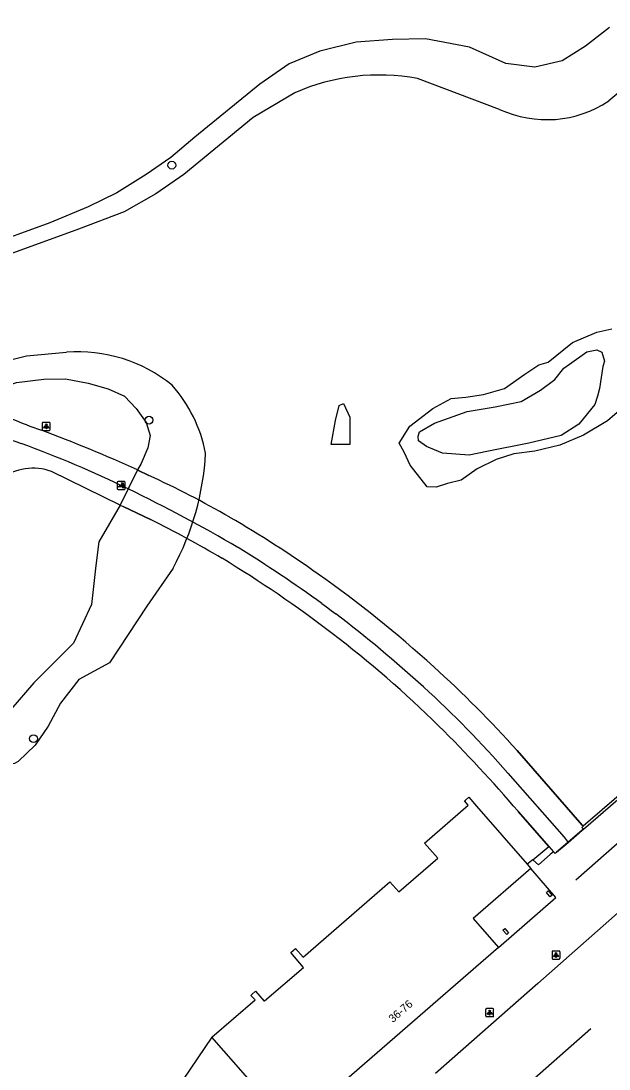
# Model space of a CAD drawing. Extents: x 155640 to 156810, y 382822 to 384046.
# Drawn here: x 156439.7 to 156513.2, y 383789.4 to 383920.4 of the extents above; entities that cross this region are included whole.
import ezdxf

# ---------------------------------------------------------------- set-up
doc = ezdxf.new("R2010")
doc.units = 0
for name, color, linetype in [('IMGEO_Boom', 7, 'Continuous'), ('IMGEO_Dek', 7, 'Continuous'), ('IMGEO_Fietspad_gesloten', 7, 'Continuous'), ('IMGEO_Grasland_overig', 7, 'Continuous'), ('IMGEO_Groenvoorziening', 7, 'Continuous'), ('IMGEO_Hek', 7, 'Continuous'), ('IMGEO_Lichtpunt', 7, 'Continuous'), ('IMGEO_Lijnafwatering', 7, 'Continuous'), ('IMGEO_Meer_plas_ven_vijver', 7, 'Continuous'), ('IMGEO_Muur', 7, 'Continuous'), ('IMGEO_Pand', 7, 'Continuous'), ('IMGEO_Pand_nummerreeks', 7, 'Continuous'), ('IMGEO_Pand_overbouw', 7, 'Continuous'), ('IMGEO_Poller', 7, 'Continuous'), ('IMGEO_Voetgangersgebied_open', 7, 'Continuous'), ('IMGEO_Voetpad_gesloten', 7, 'Continuous')]:
    doc.layers.add(name, color=color, linetype=linetype)

msp = doc.modelspace()

# ---------------------------------------------------------------- linework, layer by layer
at = {"layer": 'IMGEO_Boom'}
for centre in [(156458.58, 383902.33), (156455.73, 383870.47), (156441.3, 383830.68)]:
    msp.add_circle(centre, 0.489, dxfattribs=at)
at = {"layer": 'IMGEO_Dek'}
for points in [[(156455.71, 383863.56), (156454.33, 383864.24), (156454.27, 383864.27), (156452.13, 383859.87), (156452.48, 383859.7), (156455.93, 383858.04)], [(156501.83, 383821.59), (156505.68, 383817.2), (156506.27, 383816.55), (156506.48, 383816.34), (156506.64, 383816.48), (156508.08, 383817.72), (156509.85, 383819.25), (156510.01, 383819.38), (156509.8, 383819.59), (156509.97, 383819.73), (156509.84, 383819.88), (156501.72, 383829.19)]]:
    msp.add_lwpolyline(points, dxfattribs=at)
for centre, radius, start, end in [((156407.64, 383758.31), 115.71, 59.8229, 65.456), ((156388.52, 383723.16), 150.79, 59.5873, 63.4458), ((156397.92, 383740.52), 135.97, 54.5063, 60.0478), ((156387.28, 383724.79), 150.03, 52.507, 58.8657), ((156394.44, 383733.64), 143.59, 47.5855, 54.9701), ((156392.74, 383731.25), 141.57, 45.5357, 52.6667), ((156398.64, 383736.95), 138.32, 41.8243, 47.9452), ((156370.38, 383709.63), 172.67, 40.4232, 45.2677)]:
    msp.add_arc(centre, radius, start, end, dxfattribs=at)
at = {"layer": 'IMGEO_Fietspad_gesloten'}
for points in [[(156454.27, 383864.27), (156453.11, 383861.89)], [(156455.71, 383863.56), (156454.33, 383864.24), (156454.27, 383864.27), (156453.11, 383861.89)], [(156477.31, 383847.56), (156477.9, 383847.13), (156478.49, 383846.7), (156479.08, 383846.26)], [(156508.08, 383817.72), (156509.85, 383819.25), (156510.01, 383819.38), (156509.8, 383819.59), (156509.97, 383819.73), (156509.84, 383819.88), (156501.72, 383829.19)], [(156500.57, 383826.38), (156507.58, 383818.36), (156508.08, 383817.72)]]:
    msp.add_lwpolyline(points, dxfattribs=at)
for centre, radius, start, end in [((156459.34, 383918.52), 52.18, 241.9205, 250.9257), ((156449.16, 383897.12), 31.01, 236.13, 252.313), ((156376.78, 383693.33), 187.68, 65.6141, 69.5712), ((156391.29, 383734.93), 141.21, 64.034, 69.9343), ((156407.64, 383758.31), 115.71, 59.8229, 65.456), ((156374.93, 383698.79), 180.86, 59.4572, 64.3905), ((156397.92, 383740.52), 135.97, 54.5063, 60.0478), ((156382.67, 383717.37), 160.95, 53.9824, 58.4658), ((156394.44, 383733.64), 143.59, 47.5855, 54.9701), ((156371.97, 383706.5), 176.08, 47.895, 52.536), ((156398.64, 383736.95), 138.32, 41.8243, 47.9452), ((156396.79, 383735.25), 138.11, 41.2853, 47.5365)]:
    msp.add_arc(centre, radius, start, end, dxfattribs=at)
at = {"layer": 'IMGEO_Grasland_overig'}
msp.add_lwpolyline([(156512.42, 383877.17), (156512.02, 383874.44), (156511.75, 383873.47), (156511.42, 383872.41), (156509.4, 383869.98), (156507.21, 383868.56), (156503.16, 383867.58), (156497.93, 383866.55), (156495.73, 383866.11), (156492.38, 383866.36), (156490.38, 383867.17), (156489.39, 383867.89), (156489.37, 383868.49), (156489.52, 383869.02), (156491.38, 383870.11), (156495.49, 383871.54), (156498.98, 383872.15), (156502.2, 383872.79), (156504.62, 383874.2), (156506.42, 383875.56), (156507.56, 383876.98), (156508.24, 383877.46), (156510.42, 383879.01), (156511.66, 383879.24), (156512.3, 383878.96), (156512.62, 383877.83), (156512.42, 383877.17)], dxfattribs=at)
at = {"layer": 'IMGEO_Groenvoorziening'}
for points in [[(156513.23, 383919.55), (156510.25, 383917.22), (156507.34, 383915.39), (156503.94, 383914.57), (156500.29, 383915.04), (156495.77, 383917.07), (156490.27, 383918.13), (156486.14, 383918.02), (156481.59, 383917.7), (156477.06, 383916.59), (156473.23, 383914.99), (156469.59, 383912.45), (156461.46, 383905.85), (156458.47, 383903.31), (156455.37, 383901.16), (156451.69, 383898.86), (156448.12, 383897.12), (156443.34, 383895.14), (156434.84, 383892.06)], [(156434.78, 383872.48), (156436.85, 383874.43), (156439.16, 383875.17), (156442.59, 383875.59), (156445.3, 383875.64), (156448.14, 383875.08), (156450.64, 383874.39), (156452.65, 383873.49), (156454.13, 383871.92), (156455.37, 383870.16), (156455.88, 383868.55), (156455.6, 383867.01), (156454.74, 383865.07), (156454.27, 383864.27)], [(156452.13, 383859.87), (156449.48, 383855.27), (156449.08, 383852.3), (156448.55, 383847.43), (156446.31, 383842.6), (156441.33, 383837.65), (156438.48, 383834.31), (156437.94, 383832.12), (156437.62, 383830.06), (156437.35, 383827.77)]]:
    msp.add_lwpolyline(points, dxfattribs=at)
at = {"layer": 'IMGEO_Hek'}
for points in [[(156454.33, 383864.24), (156455.71, 383863.56)], [(156452.13, 383859.87), (156452.48, 383859.7)], [(156455.93, 383858.04), (156452.48, 383859.7)], [(156501.72, 383829.19), (156509.84, 383819.88)], [(156505.68, 383817.2), (156501.83, 383821.59)], [(156509.84, 383819.88), (156509.97, 383819.73)]]:
    msp.add_lwpolyline(points, dxfattribs=at)
for centre, radius, start, end in [((156407.64, 383758.31), 115.71, 59.8229, 65.456), ((156388.52, 383723.16), 150.79, 59.5873, 63.4458), ((156397.92, 383740.52), 135.97, 54.5063, 60.0478), ((156387.28, 383724.79), 150.03, 52.507, 58.8657), ((156394.44, 383733.64), 143.59, 47.5855, 54.9701), ((156392.74, 383731.25), 141.57, 45.5357, 52.6667), ((156398.64, 383736.95), 138.32, 41.8243, 47.9452), ((156370.38, 383709.63), 172.67, 40.4232, 45.2677)]:
    msp.add_arc(centre, radius, start, end, dxfattribs=at)
at = {"layer": 'IMGEO_Lichtpunt'}
for p, q in [((156442.39, 383870.11), (156442.39, 383869.3)), ((156442.39, 383870.11), (156442.39, 383869.3)), ((156443.29, 383870.2), (156442.48, 383870.2)), ((156443.29, 383870.2), (156442.48, 383870.2)), ((156442.48, 383869.2), (156443.29, 383869.2)), ((156442.48, 383869.2), (156443.29, 383869.2)), ((156443.38, 383869.3), (156443.38, 383870.11)), ((156443.38, 383869.3), (156443.38, 383870.11)), ((156506.07, 383804.04), (156506.07, 383803.23)), ((156506.07, 383804.04), (156506.07, 383803.23)), ((156506.97, 383804.13), (156506.17, 383804.13)), ((156506.97, 383804.13), (156506.17, 383804.13)), ((156507.07, 383803.23), (156507.07, 383804.04)), ((156507.07, 383803.23), (156507.07, 383804.04)), ((156506.17, 383803.14), (156506.97, 383803.14)), ((156506.17, 383803.14), (156506.97, 383803.14)), ((156497.78, 383796.85), (156497.78, 383796.04)), ((156497.78, 383796.85), (156497.78, 383796.04)), ((156498.69, 383796.95), (156497.88, 383796.95)), ((156498.69, 383796.95), (156497.88, 383796.95)), ((156497.88, 383795.95), (156498.69, 383795.95)), ((156497.88, 383795.95), (156498.69, 383795.95)), ((156498.78, 383796.04), (156498.78, 383796.85)), ((156498.78, 383796.04), (156498.78, 383796.85))]:
    msp.add_line(p, q, dxfattribs=at)
for points in [[(156442.76, 383869.77), (156442.8, 383869.74), (156442.61, 383869.48), (156442.57, 383869.51), (156442.76, 383869.77)], [(156442.86, 383869.72), (156442.91, 383869.72), (156442.91, 383869.4), (156442.86, 383869.4), (156442.86, 383869.72)], [(156442.97, 383869.74), (156443.01, 383869.77), (156443.2, 383869.51), (156443.16, 383869.48), (156442.97, 383869.74)], [(156506.45, 383803.7), (156506.49, 383803.67), (156506.3, 383803.41), (156506.26, 383803.44), (156506.45, 383803.7)], [(156506.55, 383803.65), (156506.6, 383803.65), (156506.6, 383803.33), (156506.55, 383803.33), (156506.55, 383803.65)], [(156506.66, 383803.67), (156506.7, 383803.7), (156506.88, 383803.44), (156506.85, 383803.41), (156506.66, 383803.67)], [(156498.16, 383796.51), (156498.2, 383796.49), (156498.01, 383796.22), (156497.97, 383796.25), (156498.16, 383796.51)], [(156498.26, 383796.47), (156498.31, 383796.47), (156498.31, 383796.14), (156498.26, 383796.14), (156498.26, 383796.47)], [(156498.37, 383796.49), (156498.41, 383796.51), (156498.6, 383796.25), (156498.56, 383796.22), (156498.37, 383796.49)]]:
    msp.add_lwpolyline(points, dxfattribs=at)
for centre in [(156442.89, 383869.9), (156506.57, 383803.84), (156498.28, 383796.65)]:
    msp.add_circle(centre, 0.0994, dxfattribs=at)
for centre, start, end in [((156442.48, 383870.11), 90, 180), ((156442.48, 383870.11), 90, 180), ((156442.48, 383869.3), 180, 270), ((156442.48, 383869.3), 180, 270), ((156443.29, 383870.11), 0, 90), ((156443.29, 383870.11), 0, 90), ((156443.29, 383869.3), 270, 0), ((156443.29, 383869.3), 270, 360), ((156506.17, 383804.04), 90, 180), ((156506.17, 383804.04), 90, 180), ((156506.97, 383804.04), 0, 90), ((156506.97, 383804.04), 0, 90), ((156506.17, 383803.23), 180, 270), ((156506.17, 383803.23), 180, 270), ((156506.97, 383803.23), 270, 0), ((156506.97, 383803.23), 270, 360), ((156497.88, 383796.85), 90, 180), ((156497.88, 383796.85), 90, 180), ((156497.88, 383796.04), 180, 270), ((156497.88, 383796.04), 180, 270), ((156498.69, 383796.85), 0, 90), ((156498.69, 383796.85), 0, 90), ((156498.69, 383796.04), 270, 0), ((156498.69, 383796.04), 270, 360)]:
    msp.add_arc(centre, 0.0946, start, end, dxfattribs=at)
at = {"layer": 'IMGEO_Lijnafwatering'}
for points in [[(156518.01, 383820.86), (156509.03, 383812.99)], [(156517.1, 383811.35), (156504.3, 383800.09)], [(156504.3, 383800.09), (156491.53, 383788.85)], [(156498.95, 383783.94), (156510.91, 383794.44)]]:
    msp.add_lwpolyline(points, dxfattribs=at)
at = {"layer": 'IMGEO_Meer_plas_ven_vijver'}
for points in [[(156525.12, 383920.35), (156513.17, 383910.36)], [(156499.53, 383909.31), (156489.26, 383913.17)], [(156473.95, 383911.38), (156468.73, 383908.3), (156460.07, 383901.16), (156456.57, 383898.77), (156452.63, 383896.51), (156446.94, 383894.32), (156435.55, 383890.23), (156429.43, 383888.05), (156419.86, 383885.57), (156417.85, 383884.58), (156412.79, 383883.05), (156406.5, 383879.69)], [(156499.08, 383865.54), (156496.7, 383864.39), (156494.74, 383862.97), (156493.03, 383862.54), (156491.61, 383862.11), (156490.46, 383862.13), (156488.33, 383864.83), (156487.61, 383866.48), (156486.97, 383867.61), (156488.32, 383869.73), (156491.19, 383871.95), (156493.49, 383873.18), (156495.3, 383873.34), (156497.52, 383873.67), (156500.15, 383874.41), (156502.69, 383876.22), (156504.42, 383877.37), (156505.57, 383877.7), (156508.61, 383880.16), (156511.65, 383881.47), (156513.54, 383881.88)], [(156422.64, 383871.06), (156424.67, 383872.17), (156429.66, 383875.18), (156435.26, 383877.22), (156440.44, 383878.51), (156445.43, 383878.97)], [(156479.04, 383870.43), (156479.49, 383872.31), (156480.03, 383872.56), (156480.83, 383870.83), (156480.83, 383867.42), (156478.47, 383867.42), (156479.04, 383870.43)], [(156515.1, 383872.19), (156513, 383870.37), (156510, 383868.58), (156507.05, 383867.35), (156503.93, 383866.61), (156501.3, 383866.28), (156499.08, 383865.54)], [(156458.74, 383851.99), (156455.47, 383847.25), (156450.79, 383840.16), (156446.97, 383838.07), (156444.69, 383835.11), (156443.15, 383832.25), (156441.52, 383829.86), (156439.38, 383827.8), (156438.92, 383827.57), (156438.51, 383827.51), (156437.96, 383827.59), (156437.35, 383827.77)]]:
    msp.add_lwpolyline(points, dxfattribs=at)
for centre, radius, start, end in [((156484.5, 383887.41), 26.19, 79.5305, 113.7702), ((156505.4, 383922.07), 14.05, 245.2987, 303.5585), ((156446.8, 383860.24), 18.78, 51.0389, 94.1926), ((156445.17, 383862.94), 17.95, 10.93, 41.535), ((156428.85, 383868.21), 34, 331.5161, 356.8601)]:
    msp.add_arc(centre, radius, start, end, dxfattribs=at)
at = {"layer": 'IMGEO_Muur'}
for points in [[(156520.99, 383827.32), (156518.61, 383827.19), (156512.33, 383821.77), (156509.97, 383819.73), (156509.8, 383819.59), (156510.01, 383819.38)], [(156510.01, 383819.38), (156518.56, 383826.76), (156518.72, 383826.9), (156521, 383827.02)], [(156503.68, 383815.54), (156505.68, 383817.2), (156506.27, 383816.55)], [(156506.27, 383816.55), (156505.85, 383816.19), (156504.38, 383814.92), (156503.68, 383815.54)]]:
    msp.add_lwpolyline(points, dxfattribs=at)
at = {"layer": 'IMGEO_Pand'}
for points in [[(156463.56, 383793.36), (156468.97, 383798.02), (156468.45, 383798.6), (156468.56, 383798.7), (156469.01, 383799.11), (156470.12, 383797.86), (156470.17, 383797.9), (156475.01, 383802.1), (156473.43, 383803.97), (156474.03, 383804.47), (156474.98, 383803.36), (156485.83, 383812.8), (156486.95, 383811.52), (156491.79, 383815.75), (156490.15, 383817.63), (156495.58, 383822.36), (156495.13, 383822.89), (156495.25, 383823), (156495.66, 383823.37), (156496.62, 383822.26), (156502.95, 383815)], [(156502.95, 383815), (156503.41, 383814.47), (156496.22, 383808.21), (156499.37, 383804.6), (156473.48, 383782.1), (156463.56, 383793.36)], [(156505.37, 383811.45), (156505.6, 383811.65), (156506.07, 383811.11), (156505.84, 383810.91), (156505.76, 383811), (156505.37, 383811.45)], [(156499.94, 383806.74), (156500.17, 383806.94), (156500.64, 383806.4), (156500.41, 383806.2), (156499.94, 383806.74)]]:
    msp.add_lwpolyline(points, dxfattribs=at)
at = {"layer": 'IMGEO_Pand_overbouw'}
msp.add_lwpolyline([(156503.41, 383814.47), (156496.22, 383808.21), (156499.37, 383804.6), (156506.55, 383810.84)], close=True, dxfattribs=at)
at = {"layer": 'IMGEO_Poller'}
for p, q in [((156451.76, 383862.71), (156451.76, 383861.9)), ((156451.76, 383862.71), (156451.76, 383861.9)), ((156452.66, 383862.81), (156451.86, 383862.81)), ((156452.66, 383862.81), (156451.86, 383862.81)), ((156452.76, 383861.9), (156452.76, 383862.71)), ((156452.76, 383861.9), (156452.76, 383862.71)), ((156451.86, 383861.81), (156452.66, 383861.81)), ((156451.86, 383861.81), (156452.66, 383861.81))]:
    msp.add_line(p, q, dxfattribs=at)
for points in [[(156452.44, 383862.54), (156452.43, 383862.46), (156452.3, 383862.67)], [(156452.3, 383862.67), (156452.53, 383862.6), (156452.46, 383862.57)], [(156452.4, 383862.16), (156451.88, 383862.16), (156452.31, 383862.44)], [(156452.46, 383861.99), (156452.52, 383862.22), (156452.55, 383862.15)], [(156452.59, 383862.13), (156452.66, 383862.12), (156452.46, 383861.99)]]:
    msp.add_lwpolyline(points, dxfattribs=at)
for centre, radius, start, end in [((156451.86, 383862.71), 0.0946, 90, 180), ((156451.86, 383862.71), 0.0946, 90, 180), ((156452.08, 383862.22), 0.516, 349.3569, 42.2912), ((156452.66, 383862.71), 0.0946, 0, 90), ((156452.66, 383862.71), 0.0946, 0, 90), ((156451.86, 383861.9), 0.0946, 180, 270), ((156451.86, 383861.9), 0.0946, 180, 270), ((156452.07, 383862.21), 0.332, 351.3247, 42.4854), ((156452.08, 383862.22), 0.476, 351.7527, 41.1691), ((156452.66, 383861.9), 0.0946, 270, 0), ((156452.66, 383861.9), 0.0946, 270, 0)]:
    msp.add_arc(centre, radius, start, end, dxfattribs=at)
at = {"layer": 'IMGEO_Voetgangersgebied_open'}
for points in [[(156510.01, 383819.38), (156509.85, 383819.25), (156506.64, 383816.48), (156506.48, 383816.34), (156506.27, 383816.55)], [(156503.68, 383815.54), (156502.95, 383815)], [(156463.56, 383793.36), (156460, 383788.09)]]:
    msp.add_lwpolyline(points, dxfattribs=at)
at = {"layer": 'IMGEO_Voetpad_gesloten'}
for points in [[(156452.13, 383859.87), (156443.54, 383864.07)], [(156453.11, 383861.89), (156452.13, 383859.87)], [(156453.11, 383861.89), (156452.13, 383859.87), (156452.48, 383859.7), (156455.93, 383858.04)], [(156501.83, 383821.59), (156505.68, 383817.2), (156506.27, 383816.55), (156506.48, 383816.34), (156506.64, 383816.48), (156508.08, 383817.72)]]:
    msp.add_lwpolyline(points, dxfattribs=at)
for centre, radius, start, end in [((156441.23, 383857.49), 6.97, 70.6042, 125.2967), ((156388.52, 383723.16), 150.79, 59.5873, 63.4458), ((156387.28, 383724.79), 150.03, 52.507, 58.8657), ((156392.74, 383731.25), 141.57, 45.5357, 52.6667), ((156370.38, 383709.63), 172.67, 40.4232, 45.2677)]:
    msp.add_arc(centre, radius, start, end, dxfattribs=at)

# ---------------------------------------------------------------- texts
at = {"layer": 'IMGEO_Pand_nummerreeks'}
msp.add_text('36-76', height=1, rotation=40.8003, dxfattribs=at).set_placement((156486.18, 383795.13))

doc.saveas('drawing.dxf')
